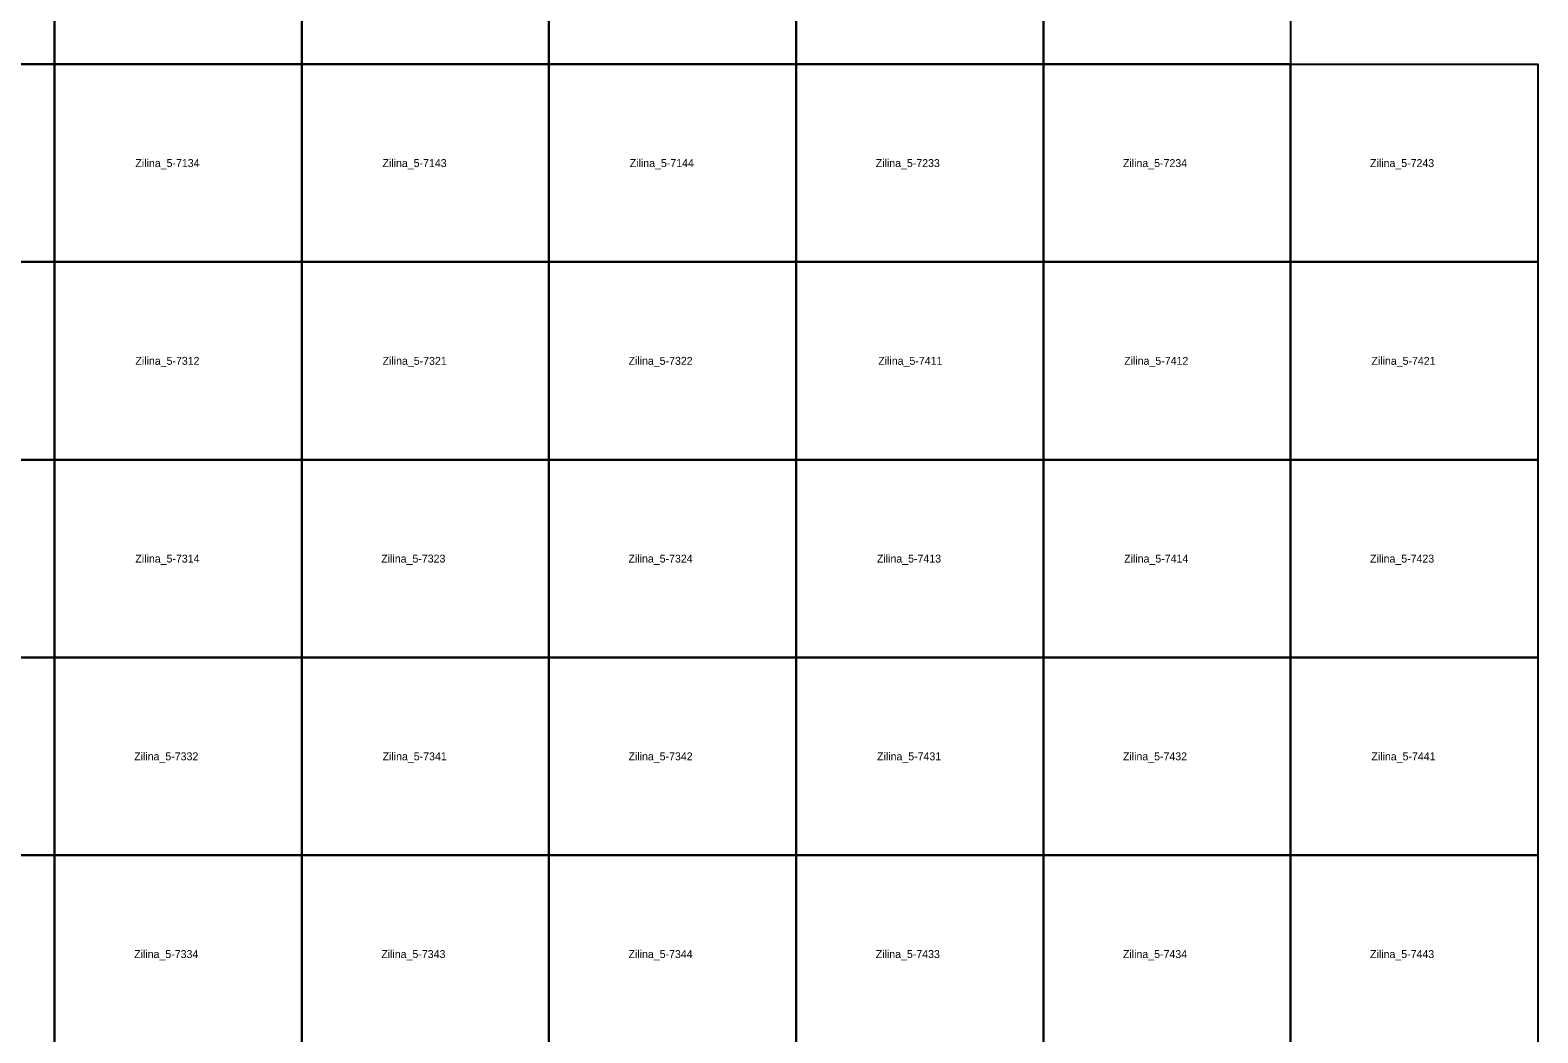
# Model space of a CAD drawing. Extents: x -445938 to -437812, y -1177250 to -1169500.
# Drawn here: x -439718 to -437812, y -1175975 to -1174707 of the extents above; entities that cross this region are included whole.
import ezdxf

# ---------------------------------------------------------------- set-up
doc = ezdxf.new("R2010")
doc.units = 0
for name, color, linetype in [('Vrstva 1', 7, 'Continuous'), ('Vrstva 4', 7, 'Continuous'), ('Vrstva 6', 7, 'Continuous')]:
    doc.layers.add(name, color=color, linetype=linetype)

msp = doc.modelspace()

# ---------------------------------------------------------------- linework, layer by layer
at = {"layer": 'Vrstva 1'}
msp.add_lwpolyline([(-440937.5, -1172000), (-440625, -1172000), (-440625, -1173000), (-440000, -1173000), (-440000, -1173500), (-439375, -1173500), (-439375, -1173750), (-438750, -1173750), (-438750, -1174000), (-438125, -1174000), (-438125, -1174750), (-437812.5, -1174750), (-437812.5, -1176750), (-438125, -1176750), (-438125, -1177000), (-438437.5, -1177000), (-438437.5, -1177250), (-439687.5, -1177250), (-439687.5, -1176750), (-440625, -1176750), (-440625, -1175500), (-441562.5, -1175500)], dxfattribs=at)
at = {"layer": 'Vrstva 4'}
for points in [[(-439687.5, -1174500), (-439687.5, -1174750), (-440000, -1174750), (-440000, -1174500)], [(-439375, -1174500), (-439375, -1174750), (-439687.5, -1174750), (-439687.5, -1174500)], [(-439062.5, -1174500), (-439062.5, -1174750), (-439375, -1174750), (-439375, -1174500)], [(-438750, -1174500), (-438750, -1174750), (-439062.5, -1174750), (-439062.5, -1174500)], [(-438437.5, -1174500), (-438437.5, -1174750), (-438750, -1174750), (-438750, -1174500)], [(-438125, -1174500), (-438125, -1174750), (-438437.5, -1174750), (-438437.5, -1174500)], [(-439687.5, -1174750), (-439687.5, -1175000), (-440000, -1175000), (-440000, -1174750)], [(-439375, -1174750), (-439375, -1175000), (-439687.5, -1175000), (-439687.5, -1174750)], [(-439062.5, -1174750), (-439062.5, -1175000), (-439375, -1175000), (-439375, -1174750)], [(-438750, -1174750), (-438750, -1175000), (-439062.5, -1175000), (-439062.5, -1174750)], [(-438437.5, -1174750), (-438437.5, -1175000), (-438750, -1175000), (-438750, -1174750)], [(-438125, -1174750), (-438125, -1175000), (-438437.5, -1175000), (-438437.5, -1174750)], [(-437812.5, -1174750), (-437812.5, -1175000), (-438125, -1175000), (-438125, -1174750)], [(-439687.5, -1175000), (-439687.5, -1175250), (-440000, -1175250), (-440000, -1175000)], [(-439375, -1175000), (-439375, -1175250), (-439687.5, -1175250), (-439687.5, -1175000)], [(-439062.5, -1175000), (-439062.5, -1175250), (-439375, -1175250), (-439375, -1175000)], [(-438750, -1175000), (-438750, -1175250), (-439062.5, -1175250), (-439062.5, -1175000)], [(-438437.5, -1175000), (-438437.5, -1175250), (-438750, -1175250), (-438750, -1175000)], [(-438125, -1175000), (-438125, -1175250), (-438437.5, -1175250), (-438437.5, -1175000)], [(-437812.5, -1175000), (-437812.5, -1175250), (-438125, -1175250), (-438125, -1175000)], [(-439687.5, -1175250), (-439687.5, -1175500), (-440000, -1175500), (-440000, -1175250)], [(-439375, -1175250), (-439375, -1175500), (-439687.5, -1175500), (-439687.5, -1175250)], [(-439062.5, -1175250), (-439062.5, -1175500), (-439375, -1175500), (-439375, -1175250)], [(-438750, -1175250), (-438750, -1175500), (-439062.5, -1175500), (-439062.5, -1175250)], [(-438437.5, -1175250), (-438437.5, -1175500), (-438750, -1175500), (-438750, -1175250)], [(-438125, -1175250), (-438125, -1175500), (-438437.5, -1175500), (-438437.5, -1175250)], [(-437812.5, -1175250), (-437812.5, -1175500), (-438125, -1175500), (-438125, -1175250)], [(-439687.5, -1175500), (-439687.5, -1175750), (-440000, -1175750), (-440000, -1175500)], [(-439375, -1175500), (-439375, -1175750), (-439687.5, -1175750), (-439687.5, -1175500)], [(-439062.5, -1175500), (-439062.5, -1175750), (-439375, -1175750), (-439375, -1175500)], [(-438750, -1175500), (-438750, -1175750), (-439062.5, -1175750), (-439062.5, -1175500)], [(-438437.5, -1175500), (-438437.5, -1175750), (-438750, -1175750), (-438750, -1175500)], [(-438125, -1175500), (-438125, -1175750), (-438437.5, -1175750), (-438437.5, -1175500)], [(-437812.5, -1175500), (-437812.5, -1175750), (-438125, -1175750), (-438125, -1175500)], [(-439687.5, -1175750), (-439687.5, -1176000), (-440000, -1176000), (-440000, -1175750)], [(-439375, -1175750), (-439375, -1176000), (-439687.5, -1176000), (-439687.5, -1175750)], [(-439062.5, -1175750), (-439062.5, -1176000), (-439375, -1176000), (-439375, -1175750)], [(-438750, -1175750), (-438750, -1176000), (-439062.5, -1176000), (-439062.5, -1175750)], [(-438437.5, -1175750), (-438437.5, -1176000), (-438750, -1176000), (-438750, -1175750)], [(-438125, -1175750), (-438125, -1176000), (-438437.5, -1176000), (-438437.5, -1175750)], [(-437812.5, -1175750), (-437812.5, -1176000), (-438125, -1176000), (-438125, -1175750)]]:
    msp.add_lwpolyline(points, close=True, dxfattribs=at)

# ---------------------------------------------------------------- texts
at = {"layer": 'Vrstva 6'}
for s, p in [('Zilina_5-7134', (-439585.222, -1174880)), ('Zilina_5-7143', (-439272.879, -1174880)), ('Zilina_5-7144', (-438960.379, -1174880)), ('Zilina_5-7233', (-438649.414, -1174880)), ('Zilina_5-7234', (-438336.914, -1174880)), ('Zilina_5-7243', (-438024.572, -1174880)), ('Zilina_5-7312', (-439585.222, -1175130)), ('Zilina_5-7321', (-439272.721, -1175130)), ('Zilina_5-7322', (-438961.914, -1175130)), ('Zilina_5-7411', (-438646.186, -1175130)), ('Zilina_5-7412', (-438335.379, -1175130)), ('Zilina_5-7421', (-438022.878, -1175130)), ('Zilina_5-7314', (-439585.222, -1175380)), ('Zilina_5-7323', (-439274.414, -1175380)), ('Zilina_5-7324', (-438961.914, -1175380)), ('Zilina_5-7413', (-438647.879, -1175380)), ('Zilina_5-7414', (-438335.379, -1175380)), ('Zilina_5-7423', (-438024.572, -1175380)), ('Zilina_5-7332', (-439586.756, -1175630)), ('Zilina_5-7341', (-439272.721, -1175630)), ('Zilina_5-7342', (-438961.914, -1175630)), ('Zilina_5-7431', (-438647.721, -1175630)), ('Zilina_5-7432', (-438336.914, -1175630)), ('Zilina_5-7441', (-438022.878, -1175630)), ('Zilina_5-7334', (-439586.756, -1175880)), ('Zilina_5-7343', (-439274.414, -1175880)), ('Zilina_5-7344', (-438961.914, -1175880)), ('Zilina_5-7433', (-438649.414, -1175880)), ('Zilina_5-7434', (-438336.914, -1175880)), ('Zilina_5-7443', (-438024.572, -1175880))]:
    msp.add_text(s, height=10, dxfattribs=at).set_placement(p)

doc.saveas('drawing.dxf')
